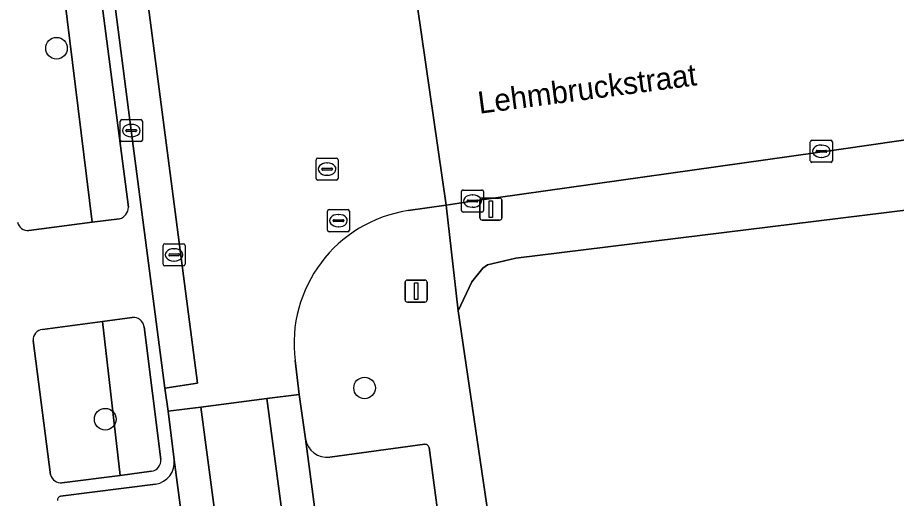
# Model space of a CAD drawing. Extents: x 160554 to 161248, y 385329 to 386506.
# Drawn here: x 161105.66 to 161145.43, y 385709.34 to 385731.11 of the extents above; entities that cross this region are included whole.
import ezdxf

# ---------------------------------------------------------------- set-up
doc = ezdxf.new("R2010")
doc.units = 0
for name, color, linetype in [('IMGEO_Boom', 7, 'Continuous'), ('IMGEO_Groenvoorziening', 7, 'Continuous'), ('IMGEO_Kolk', 7, 'Continuous'), ('IMGEO_Lichtmast', 7, 'Continuous'), ('IMGEO_Openbare_ruimte_label', 7, 'Continuous'), ('IMGEO_Parkeervlak_open', 7, 'Continuous'), ('IMGEO_Rijbaan_lokaal_gesloten', 7, 'Continuous'), ('IMGEO_Rijbaan_lokaal_open', 7, 'Continuous'), ('IMGEO_Rioolput', 7, 'Continuous'), ('IMGEO_Voetpad_open', 7, 'Continuous')]:
    doc.layers.add(name, color=color, linetype=linetype)

msp = doc.modelspace()

# ---------------------------------------------------------------- linework, layer by layer
at = {"layer": 'IMGEO_Boom'}
for centre in [(161107.423, 385729.722), (161121.364, 385714.338), (161109.627, 385712.923)]:
    msp.add_circle(centre, 0.489, dxfattribs=at)
at = {"layer": 'IMGEO_Groenvoorziening'}
for points in [[(161106.173, 385721.467), (161109.037, 385721.838), (161107.656, 385733.133)], [(161108.832, 385733.277), (161107.656, 385733.133), (161109.037, 385721.838), (161110.273, 385721.998)], [(161110.674, 385722.524), (161109.344, 385732.833)], [(161147.059, 385722.533), (161128.206, 385720.222), (161126.919, 385719.912), (161126.713, 385719.758), (161126.224, 385719.145), (161125.602, 385717.829), (161127.611, 385704.206), (161130.563, 385704.6), (161130.373, 385706.021), (161140.397, 385707.34), (161154.867, 385597.365), (161145.041, 385596.072), (161144.923, 385596.974), (161141.874, 385596.574), (161142.167, 385594.329)], [(161110.851, 385717.535), (161109.498, 385717.352), (161110.302, 385710.38), (161111.722, 385710.563)], [(161109.498, 385717.352), (161106.795, 385716.986)], [(161107.671, 385710.042), (161110.302, 385710.38), (161109.498, 385717.352)], [(161112.143, 385711.099), (161111.39, 385717.113)], [(161106.369, 385716.486), (161107.155, 385710.406)]]:
    msp.add_lwpolyline(points, dxfattribs=at)
for centre, radius, start, end in [((161110.14, 385722.515), 0.534, 284.4297, 0.9296), ((161106.129, 385721.944), 0.479, 192.0028, 275.2667), ((161110.887, 385717.026), 0.51, 9.8059, 94.0771), ((161106.824, 385716.53), 0.457, 93.6041, 185.5339), ((161111.639, 385711.061), 0.505, 279.4349, 4.2696), ((161107.627, 385710.527), 0.487, 194.412, 275.1877)]:
    msp.add_arc(centre, radius, start, end, dxfattribs=at)
at = {"layer": 'IMGEO_Kolk'}
for p, q in [((161110.307, 385725.566), (161110.307, 385726.418)), ((161110.382, 385726.492), (161111.234, 385726.492)), ((161110.795, 385726.272), (161110.82, 385726.272)), ((161111.308, 385726.418), (161111.308, 385725.566)), ((161110.566, 385725.986), (161110.566, 385725.998)), ((161111.004, 385725.949), (161110.606, 385725.949)), ((161110.609, 385726.035), (161111.007, 385726.035)), ((161111.05, 385725.998), (161111.05, 385725.986)), ((161111.234, 385725.492), (161110.382, 385725.492)), ((161110.818, 385725.712), (161110.793, 385725.712)), ((161141.534, 385724.629), (161141.534, 385725.481)), ((161141.609, 385725.555), (161142.461, 385725.555)), ((161142.535, 385725.481), (161142.535, 385724.629)), ((161141.793, 385725.049), (161141.793, 385725.061)), ((161142.231, 385725.012), (161141.833, 385725.012)), ((161141.836, 385725.098), (161142.234, 385725.098)), ((161142.022, 385725.335), (161142.047, 385725.335)), ((161142.277, 385725.061), (161142.277, 385725.049)), ((161142.045, 385724.775), (161142.02, 385724.775)), ((161142.461, 385724.555), (161141.609, 385724.555)), ((161125.747, 385722.376), (161125.747, 385723.228)), ((161125.822, 385723.302), (161126.674, 385723.302)), ((161126.235, 385723.082), (161126.26, 385723.082)), ((161126.748, 385723.228), (161126.748, 385722.376)), ((161126.006, 385722.796), (161126.006, 385722.808)), ((161126.444, 385722.759), (161126.046, 385722.759)), ((161126.049, 385722.845), (161126.447, 385722.845)), ((161126.49, 385722.808), (161126.49, 385722.796)), ((161126.674, 385722.302), (161125.822, 385722.302)), ((161126.258, 385722.522), (161126.233, 385722.522))]:
    msp.add_line(p, q, dxfattribs=at)
for points in [[(161110.307, 385725.566), (161110.307, 385726.418)], [(161110.382, 385726.492), (161111.234, 385726.492)], [(161111.308, 385726.418), (161111.308, 385725.566)], [(161111.234, 385725.492), (161110.382, 385725.492)], [(161141.534, 385724.629), (161141.534, 385725.481)], [(161141.609, 385725.555), (161142.461, 385725.555)], [(161142.535, 385725.481), (161142.535, 385724.629)], [(161142.461, 385724.555), (161141.609, 385724.555)], [(161125.747, 385722.376), (161125.747, 385723.228)], [(161125.822, 385723.302), (161126.674, 385723.302)], [(161126.748, 385723.228), (161126.748, 385722.376)], [(161126.674, 385722.302), (161125.822, 385722.302)]]:
    msp.add_lwpolyline(points, dxfattribs=at)
for centre, radius, start, end in [((161110.384, 385726.416), 0.0765, 91.552, 178.448), ((161110.384, 385726.416), 0.0765, 91.552, 178.448), ((161111.232, 385726.416), 0.0765, 1.552, 88.448), ((161111.232, 385726.416), 0.0765, 1.552, 88.448), ((161110.606, 385725.995), 0.0403, 85.8775, 175.7526), ((161110.603, 385725.985), 0.0366, 178.938, 274.7102), ((161111.007, 385725.992), 0.043, 264.8664, 352.4533), ((161111.011, 385725.997), 0.0386, 1.7309, 96.639), ((161110.384, 385725.568), 0.0765, 181.552, 268.448), ((161110.384, 385725.568), 0.0765, 181.552, 268.448), ((161111.232, 385725.568), 0.0765, 271.552, 358.448), ((161111.232, 385725.568), 0.0765, 271.552, 358.448), ((161141.611, 385725.479), 0.0765, 91.552, 178.448), ((161141.611, 385725.479), 0.0765, 91.552, 178.448), ((161142.459, 385725.479), 0.0765, 1.552, 88.448), ((161142.459, 385725.479), 0.0765, 1.552, 88.448), ((161141.833, 385725.058), 0.0403, 85.8775, 175.7526), ((161141.83, 385725.048), 0.0366, 178.938, 274.7102), ((161142.234, 385725.055), 0.043, 264.8664, 352.4533), ((161142.238, 385725.06), 0.0386, 1.7309, 96.639), ((161141.611, 385724.631), 0.0765, 181.552, 268.448), ((161141.611, 385724.631), 0.0765, 181.552, 268.448), ((161142.459, 385724.631), 0.0765, 271.552, 358.448), ((161142.459, 385724.631), 0.0765, 271.552, 358.448), ((161125.824, 385723.226), 0.0765, 91.552, 178.448), ((161125.824, 385723.226), 0.0765, 91.552, 178.448), ((161126.672, 385723.226), 0.0765, 1.552, 88.448), ((161126.672, 385723.226), 0.0765, 1.552, 88.448), ((161126.046, 385722.805), 0.0403, 85.8775, 175.7526), ((161126.043, 385722.795), 0.0366, 178.938, 274.7102), ((161126.447, 385722.802), 0.043, 264.8664, 352.4533), ((161126.451, 385722.807), 0.0386, 1.7309, 96.639), ((161125.824, 385722.378), 0.0765, 181.552, 268.448), ((161125.824, 385722.378), 0.0765, 181.552, 268.448), ((161126.672, 385722.378), 0.0765, 271.552, 358.448), ((161126.672, 385722.378), 0.0765, 271.552, 358.448)]:
    msp.add_arc(centre, radius, start, end, dxfattribs=at)
for centre, major_axis, ratio, start_param, end_param in [((161110.794, 385725.992), (-0.387, 0.002), 0.722429, 4.712389, 7.853982), ((161110.819, 385725.992), (-0.39, 0.002), 0.717154, 1.570796, 4.712389), ((161142.021, 385725.055), (-0.387, 0.002), 0.722429, 4.712389, 7.853982), ((161142.046, 385725.055), (-0.39, 0.002), 0.717154, 1.570796, 4.712389), ((161126.234, 385722.802), (-0.387, 0.002), 0.722429, 4.712389, 7.853982), ((161126.259, 385722.802), (-0.39, 0.002), 0.717154, 1.570796, 4.712389)]:
    msp.add_ellipse(centre, major_axis=major_axis, ratio=ratio, start_param=start_param, end_param=end_param, dxfattribs=at)
at = {"layer": 'IMGEO_Lichtmast'}
for p, q in [((161126.586, 385722.038), (161126.586, 385722.838)), ((161126.586, 385722.838), (161126.586, 385722.038)), ((161126.686, 385722.938), (161127.476, 385722.938)), ((161127.476, 385722.938), (161126.686, 385722.938)), ((161127.576, 385722.838), (161127.576, 385722.038)), ((161127.576, 385722.038), (161127.576, 385722.838)), ((161127.476, 385721.938), (161126.686, 385721.938)), ((161126.686, 385721.938), (161127.476, 385721.938)), ((161123.199, 385718.324), (161123.199, 385719.124)), ((161123.199, 385719.124), (161123.199, 385718.324)), ((161123.299, 385719.224), (161124.089, 385719.224)), ((161124.089, 385719.224), (161123.299, 385719.224)), ((161124.189, 385719.124), (161124.189, 385718.324)), ((161124.189, 385718.324), (161124.189, 385719.124)), ((161124.089, 385718.224), (161123.299, 385718.224)), ((161123.299, 385718.224), (161124.089, 385718.224))]:
    msp.add_line(p, q, dxfattribs=at)
for points in [[(161127.006, 385722.813), (161127.156, 385722.813), (161127.156, 385722.063), (161127.006, 385722.063), (161127.006, 385722.813)], [(161123.619, 385719.099), (161123.769, 385719.099), (161123.769, 385718.349), (161123.619, 385718.349), (161123.619, 385719.099)]]:
    msp.add_lwpolyline(points, dxfattribs=at)
for centre, start, end in [((161126.686, 385722.838), 90, 180), ((161126.686, 385722.838), 90, 180), ((161127.476, 385722.838), 0, 90), ((161127.476, 385722.838), 360, 90), ((161126.686, 385722.038), 180, 270), ((161126.686, 385722.038), 180, 270), ((161127.476, 385722.038), 270, 0), ((161127.476, 385722.038), 270, 0), ((161123.299, 385719.124), 90, 180), ((161123.299, 385719.124), 90, 180), ((161124.089, 385719.124), 0, 90), ((161124.089, 385719.124), 360, 90), ((161123.299, 385718.324), 180, 270), ((161123.299, 385718.324), 180, 270), ((161124.089, 385718.324), 270, 0), ((161124.089, 385718.324), 270, 0)]:
    msp.add_arc(centre, 0.1, start, end, dxfattribs=at)
at = {"layer": 'IMGEO_Parkeervlak_open'}
for points in [[(161118.687, 385712.039), (161119.808, 385703.6), (161125.232, 385704.311), (161125.21, 385704.708), (161124.281, 385711.637)], [(161124.094, 385711.785), (161119.791, 385711.204)], [(161115.687, 385688.859), (161112.752, 385711.087)], [(161111.899, 385709.984), (161107.605, 385709.433)]]:
    msp.add_lwpolyline(points, dxfattribs=at)
for centre, radius, start, end in [((161119.672, 385712.194), 0.997, 188.9571, 276.8395), ((161124.101, 385711.602), 0.183, 10.949, 92.3317), ((161111.754, 385710.977), 1.004, 278.3058, 6.2613), ((161107.662, 385709.24), 0.201, 106.4993, 180.8917)]:
    msp.add_arc(centre, radius, start, end, dxfattribs=at)
at = {"layer": 'IMGEO_Rijbaan_lokaal_gesloten'}
for points in [[(161109.114, 385739.295), (161109.885, 385733.092), (161109.906, 385732.917), (161110.808, 385725.992), (161112.32, 385714.335), (161113.803, 385714.55), (161110.567, 385739.457)], [(161126.304, 385654.668), (161125.101, 385663.743), (161123.982, 385672.122), (161122.934, 385680.072), (161121.351, 385691.998), (161120.302, 385699.906), (161119.808, 385703.6), (161118.687, 385712.039), (161118.403, 385714.049), (161116.941, 385713.856), (161126.361, 385642.988), (161127.841, 385643.167)], [(161113.955, 385713.475), (161112.481, 385713.283), (161112.752, 385711.087), (161115.687, 385688.859), (161115.905, 385687.322), (161117.782, 385673.171), (161117.792, 385673.096), (161119.144, 385662.893), (161119.19, 385662.67), (161120.563, 385652.257), (161121.601, 385644.555), (161121.879, 385642.406), (161122.356, 385642.474), (161123.372, 385642.618)]]:
    msp.add_lwpolyline(points, close=True, dxfattribs=at)
msp.add_lwpolyline([(161156.457, 385735.892), (161156.307, 385735.836), (161156.186, 385735.803), (161142.998, 385734.087), (161140.183, 385733.73), (161124.967, 385731.76), (161123.761, 385731.592), (161125.06, 385722.618), (161126.238, 385722.801), (161142.936, 385725.157), (161148.145, 385725.902), (161154.541, 385727.595)], dxfattribs=at)
at = {"layer": 'IMGEO_Rijbaan_lokaal_open'}
for points in [[(161115.507, 385736.425), (161115.393, 385737.319), (161115.32, 385737.885), (161114.908, 385741.08), (161113.427, 385740.879), (161110.443, 385740.527), (161108.975, 385740.332), (161109.114, 385739.295), (161110.567, 385739.457), (161113.803, 385714.55), (161112.32, 385714.335), (161112.481, 385713.283), (161113.955, 385713.475), (161116.941, 385713.856), (161118.403, 385714.049), (161118.222, 385715.575)], [(161123.329, 385722.367), (161125.06, 385722.618), (161123.761, 385731.592)]]:
    msp.add_lwpolyline(points, dxfattribs=at)
msp.add_lwpolyline([(161116.941, 385713.856), (161113.955, 385713.475), (161123.372, 385642.618), (161126.361, 385642.988)], close=True, dxfattribs=at)
msp.add_arc((161124.257, 385716.353), 6.085, 98.7712, 187.3487, dxfattribs=at)
at = {"layer": 'IMGEO_Rioolput'}
for p, q in [((161119.166, 385723.823), (161119.166, 385724.675)), ((161119.241, 385724.749), (161120.093, 385724.749)), ((161120.167, 385724.675), (161120.167, 385723.823)), ((161119.425, 385724.243), (161119.425, 385724.255)), ((161119.863, 385724.206), (161119.465, 385724.206)), ((161119.468, 385724.292), (161119.866, 385724.292)), ((161119.654, 385724.529), (161119.679, 385724.529)), ((161119.909, 385724.255), (161119.909, 385724.243)), ((161119.677, 385723.969), (161119.652, 385723.969)), ((161120.093, 385723.749), (161119.241, 385723.749)), ((161119.679, 385721.488), (161119.679, 385722.34)), ((161119.754, 385722.414), (161120.606, 385722.414)), ((161120.68, 385722.34), (161120.68, 385721.488)), ((161119.938, 385721.908), (161119.938, 385721.92)), ((161120.376, 385721.871), (161119.978, 385721.871)), ((161119.981, 385721.957), (161120.379, 385721.957)), ((161120.167, 385722.194), (161120.192, 385722.194)), ((161120.422, 385721.92), (161120.422, 385721.908)), ((161120.19, 385721.634), (161120.165, 385721.634)), ((161120.606, 385721.414), (161119.754, 385721.414)), ((161112.242, 385719.939), (161112.242, 385720.791)), ((161112.317, 385720.865), (161113.169, 385720.865)), ((161112.73, 385720.645), (161112.755, 385720.645)), ((161113.243, 385720.791), (161113.243, 385719.939)), ((161112.501, 385720.359), (161112.501, 385720.371)), ((161112.939, 385720.322), (161112.541, 385720.322)), ((161112.544, 385720.408), (161112.942, 385720.408)), ((161112.985, 385720.371), (161112.985, 385720.359)), ((161113.169, 385719.865), (161112.317, 385719.865)), ((161112.753, 385720.085), (161112.728, 385720.085))]:
    msp.add_line(p, q, dxfattribs=at)
for points in [[(161119.166, 385723.823), (161119.166, 385724.675)], [(161119.241, 385724.749), (161120.093, 385724.749)], [(161120.167, 385724.675), (161120.167, 385723.823)], [(161120.093, 385723.749), (161119.241, 385723.749)], [(161119.679, 385721.488), (161119.679, 385722.34)], [(161119.754, 385722.414), (161120.606, 385722.414)], [(161120.68, 385722.34), (161120.68, 385721.488)], [(161120.606, 385721.414), (161119.754, 385721.414)], [(161112.242, 385719.939), (161112.242, 385720.791)], [(161112.317, 385720.865), (161113.169, 385720.865)], [(161113.243, 385720.791), (161113.243, 385719.939)], [(161113.169, 385719.865), (161112.317, 385719.865)]]:
    msp.add_lwpolyline(points, dxfattribs=at)
for centre, radius, start, end in [((161119.243, 385724.673), 0.0765, 91.552, 178.448), ((161119.243, 385724.673), 0.0765, 91.552, 178.448), ((161120.091, 385724.673), 0.0765, 1.552, 88.448), ((161120.091, 385724.673), 0.0765, 1.552, 88.448), ((161119.465, 385724.252), 0.0403, 85.8775, 175.7526), ((161119.462, 385724.242), 0.0366, 178.938, 274.7102), ((161119.866, 385724.249), 0.043, 264.8664, 352.4533), ((161119.87, 385724.254), 0.0386, 1.7309, 96.639), ((161119.243, 385723.825), 0.0765, 181.552, 268.448), ((161119.243, 385723.825), 0.0765, 181.552, 268.448), ((161120.091, 385723.825), 0.0765, 271.552, 358.448), ((161120.091, 385723.825), 0.0765, 271.552, 358.448), ((161119.756, 385722.338), 0.0765, 91.552, 178.448), ((161119.756, 385722.338), 0.0765, 91.552, 178.448), ((161120.604, 385722.338), 0.0765, 1.552, 88.448), ((161120.604, 385722.338), 0.0765, 1.552, 88.448), ((161119.978, 385721.917), 0.0403, 85.8775, 175.7526), ((161119.975, 385721.907), 0.0366, 178.938, 274.7102), ((161120.379, 385721.914), 0.043, 264.8664, 352.4533), ((161120.383, 385721.919), 0.0386, 1.7309, 96.639), ((161119.756, 385721.49), 0.0765, 181.552, 268.448), ((161119.756, 385721.49), 0.0765, 181.552, 268.448), ((161120.604, 385721.49), 0.0765, 271.552, 358.448), ((161120.604, 385721.49), 0.0765, 271.552, 358.448), ((161112.319, 385720.789), 0.0765, 91.552, 178.448), ((161112.319, 385720.789), 0.0765, 91.552, 178.448), ((161113.167, 385720.789), 0.0765, 1.552, 88.448), ((161113.167, 385720.789), 0.0765, 1.552, 88.448), ((161112.541, 385720.368), 0.0403, 85.8775, 175.7526), ((161112.538, 385720.358), 0.0366, 178.938, 274.7102), ((161112.942, 385720.365), 0.043, 264.8664, 352.4533), ((161112.946, 385720.37), 0.0386, 1.7309, 96.639), ((161112.319, 385719.941), 0.0765, 181.552, 268.448), ((161112.319, 385719.941), 0.0765, 181.552, 268.448), ((161113.167, 385719.941), 0.0765, 271.552, 358.448), ((161113.167, 385719.941), 0.0765, 271.552, 358.448)]:
    msp.add_arc(centre, radius, start, end, dxfattribs=at)
for centre, major_axis, ratio, start_param, end_param in [((161119.653, 385724.249), (-0.387, 0.002), 0.722429, 4.712389, 7.853982), ((161119.678, 385724.249), (-0.39, 0.002), 0.717154, 1.570796, 4.712389), ((161120.166, 385721.914), (-0.387, 0.002), 0.722429, 4.712389, 7.853982), ((161120.191, 385721.914), (-0.39, 0.002), 0.717154, 1.570796, 4.712389), ((161112.729, 385720.365), (-0.387, 0.002), 0.722429, 4.712389, 7.853982), ((161112.754, 385720.365), (-0.39, 0.002), 0.717154, 1.570796, 4.712389)]:
    msp.add_ellipse(centre, major_axis=major_axis, ratio=ratio, start_param=start_param, end_param=end_param, dxfattribs=at)
at = {"layer": 'IMGEO_Voetpad_open'}
for points in [[(161112.752, 385711.087), (161112.481, 385713.283), (161112.32, 385714.335), (161110.808, 385725.992), (161109.906, 385732.917), (161109.885, 385733.092)], [(161109.344, 385732.833), (161110.674, 385722.524)], [(161148.145, 385725.902), (161142.936, 385725.157), (161126.238, 385722.801), (161125.06, 385722.618), (161125.602, 385717.829), (161126.224, 385719.145), (161126.713, 385719.758), (161126.919, 385719.912), (161128.206, 385720.222), (161147.059, 385722.533)], [(161136.775, 385635.582), (161135.488, 385645.432), (161134.132, 385655.805), (161132.88, 385665.385), (161131.957, 385672.448), (161130.664, 385682.353), (161129.332, 385692.539), (161127.611, 385704.206), (161125.602, 385717.829), (161125.06, 385722.618), (161123.329, 385722.367)], [(161110.273, 385721.998), (161109.037, 385721.838), (161106.173, 385721.467)], [(161106.795, 385716.986), (161109.498, 385717.352), (161110.851, 385717.535)], [(161111.39, 385717.113), (161112.143, 385711.099)], [(161107.155, 385710.406), (161106.369, 385716.486)], [(161118.222, 385715.575), (161118.403, 385714.049), (161118.687, 385712.039)], [(161119.791, 385711.204), (161124.094, 385711.785)], [(161124.281, 385711.637), (161125.21, 385704.708), (161126.379, 385704.866), (161126.895, 385700.846), (161125.729, 385700.681), (161126.802, 385692.745), (161127.981, 385692.914), (161129.551, 385681.019), (161128.374, 385680.818), (161129.416, 385672.858), (161130.6, 385673.008), (161131.8, 385664.039), (161130.603, 385663.89), (161131.504, 385657.228), (161131.677, 385655.975), (161132.861, 385656.143), (161134.374, 385644.689), (161133.183, 385644.532)], [(161111.722, 385710.563), (161110.302, 385710.38), (161107.671, 385710.042)], [(161107.605, 385709.433), (161111.899, 385709.984)]]:
    msp.add_lwpolyline(points, dxfattribs=at)
for centre, radius, start, end in [((161110.14, 385722.515), 0.534, 284.4297, 0.9296), ((161124.257, 385716.353), 6.085, 98.7712, 187.3487), ((161106.129, 385721.944), 0.479, 192.0028, 275.2667), ((161110.887, 385717.026), 0.51, 9.8059, 94.0771), ((161106.824, 385716.53), 0.457, 93.6041, 185.5339), ((161119.672, 385712.194), 0.997, 188.9571, 276.8395), ((161124.101, 385711.602), 0.183, 10.949, 92.3317), ((161111.639, 385711.061), 0.505, 279.4349, 4.2696), ((161111.754, 385710.977), 1.004, 278.3058, 6.2613), ((161107.627, 385710.527), 0.487, 194.412, 275.1877), ((161107.662, 385709.24), 0.201, 106.4993, 180.8917)]:
    msp.add_arc(centre, radius, start, end, dxfattribs=at)

# ---------------------------------------------------------------- texts
at = {"layer": 'IMGEO_Openbare_ruimte_label'}
msp.add_text('Lehmbruckstraat', height=1, rotation=7.466, dxfattribs=at).set_placement((161126.558, 385726.753))

doc.saveas('drawing.dxf')
